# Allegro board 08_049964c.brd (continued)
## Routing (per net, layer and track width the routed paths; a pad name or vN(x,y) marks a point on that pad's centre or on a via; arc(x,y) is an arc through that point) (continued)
VIN: length 4
  TOP w0.508: 55.5,64.9 55.41,64.98 R13.1
  vias: v1(10.41,40.64) v1(10.41,39.75) v1(10.41,38.86) v1(10.41,37.97) v1(10.41,37.08) v1(11.43,40.64) v1(11.43,39.75) v1(11.43,38.86) v1(11.43,37.97) v1(11.43,37.08) v1(12.57,40.64) v1(12.57,39.75) v1(12.57,38.86) v1(13.72,40.64) v1(13.72,39.75) v1(13.72,38.86) v1(49.4,63.37) v1(49.4,62.48) v1(49.4,61.34) v1(49.4,60.45) v1(50.42,63.37) v1(50.42,62.48) v1(50.42,61.34) v1(50.42,60.45) v1(51.56,63.37) v1(51.56,62.48) v1(51.56,61.34) v1(51.56,60.45) v1(52.7,63.37) v1(52.7,62.48) v1(52.7,61.34) v1(52.7,60.45)
VIN1: length 2.5
  TOP w0.305: U1.1 51.18,83.55 51.18,83.57
  vias: v1(32,73.28) v1(32,72.14) v1(32,70.99) v1(32,70.1) v1(33.02,73.28) v1(33.02,72.14) v1(33.02,70.99) v1(33.02,70.1) v1(34.29,73.28) v1(34.29,72.14) v1(34.29,70.99) v1(34.29,70.1) v1(35.43,73.28) v1(35.43,72.14) v1(35.43,70.99) v1(35.43,70.1) v1(47.24,88.9) v1(47.24,88.01) v1(47.24,84.96) v1(47.24,84.07) v1(48.13,88.9) v1(48.13,88.01) v1(48.13,84.96) v1(48.13,84.07) v1(48.95,88.9) v1(48.95,88.01) v1(48.95,84.96) v1(48.95,84.07) v1(49.78,84.96) v1(49.78,84.07)
VIN2: length 12.9
  TOP w0.203: v2(54.41,33.02) 56.32,33.02 56.67,32.67 U3.19
  L3_PWR w0.305: v1(51.82,40.64) 51.56,40.39 51.56,35.04 52.39,34.21 54.1,34.21 54.41,33.91 v2(54.41,33.02)
  vias: v1(22.99,38.35) v1(22.99,37.46) v1(22.99,36.58) v1(22.99,35.69) v1(23.88,38.35) v1(23.88,37.46) v1(23.88,36.58) v1(23.88,35.69) v1(26.8,38.35) v1(26.8,37.46) v1(26.8,36.58) v1(26.8,35.69) v1(27.69,38.35) v1(27.69,37.46) v1(27.69,36.58) v1(27.69,35.69) v1(43.56,40.51) v1(43.56,39.66) v1(44.4,40.52) v1(44.45,39.75) v1(45.29,40.52) v1(45.34,39.75) v1(46.23,40.51) v1(46.23,39.75) v1(46.99,39.5) v1(47.88,39.5)
EN/UVLO: length 44.4
  TOP w0.203: R22.1 v1(33.36,7.53)
  TOP w0.254: v2(52.67,32.06) 52.94,31.8 53.47,31.8 53.78,31.5 54.61,31.5 55.15,30.96 U3.22
  L3_PWR w0.203: v2(52.67,32.06) 52.6,32.13 52.6,32.25 52.14,32.72 49.89,32.72 48.98,31.8 41.87,31.8 38.35,28.28 38.35,18.54 32.68,12.86 32.68,8.22 v1(33.36,7.53)
FAULT: length 81.2
  TOP w0.305: DS3.C v1(2.54,85.85) ; U4.6 25.48,63.89 25.78,63.58 v1(25.78,63.12)
  BOTTOM w0.305: 11.3,85.85 11.3,74.04 21.51,63.83 25.07,63.83 v1(25.78,63.12) ; 11.3,85.85 v1(2.54,85.85) ; 11.3,85.85 38.35,85.85 FAULT.1 44.51,92.01 EN.1
FSEL4A: length 35.7
  TOP w0.203: v2(61.54,33.25) 61.54,33.19 61.15,32.79 60.48,32.79 60.17,32.48 U3.12
  L3_PWR w0.254: v1(56.52,54.36) 56.52,54.1 57.4,53.21 61.09,53.21 61.54,52.76 v2(61.54,33.25)
  BOTTOM w0.305: v1(56.52,54.36) 56.52,54.15 56.21,53.85 51.82,53.85 51.44,54.23 R23.2 R24.2
FSEL4B: length 29.9
  TOP w0.203: v2(52.96,34.92) 53.85,34.04 56.77,34.04 57.67,33.13 U3.17
  L3_PWR w0.254: v1(49.66,53.85) 49.66,52.32 53.06,48.92 53.06,35.03 v2(52.96,34.92)
  BOTTOM w0.305: v1(49.66,53.85) 49.91,54.1 R27.1 R28.1
INTVCC: length 155.5
  TOP w0.203: R17.1 v1(41.36,5.42) ; 54.6,27.88 54.68,27.96
  TOP w0.254: 54.68,27.96 U3.28
  TOP w0.305: v1(54.72,19.93) 54.72,19.96 R29.1
  TOP w0.457: v1(53.52,27.38) 54.02,27.88 54.6,27.88
  TOP w0.508: C19.2 52.86,27.09 53.15,27.38 v1(53.52,27.38)
  L3_PWR w0.203: v1(41.36,5.42) 41.66,5.71 41.66,8.38 40.51,9.52 40.51,26.42 42.93,28.83 v1(43.69,28.83)
  L3_PWR w0.254: v1(53.52,27.38) 53.47,27.38 53.32,27.23 53.18,27.23 53.17,27.21 53.16,27.21 50.8,24.85 50.8,24.13 49.02,22.35 46.99,22.35 ; 46.99,22.35 46.99,27.86 45.42,29.43 44.28,29.43 v1(43.69,28.83) ; 46.99,22.35 46.99,18.16 48.01,17.14 51.9,17.14 54.69,19.93 v1(54.72,19.93)
  L3_PWR w0.305: v1(94.23,57.66) 93.98,57.66 93.6,57.28 87.63,57.28 84.1,53.75 57.63,53.75 57.23,54.15 57.23,54.79 53.98,58.04 v1(49.91,58.04)
  BOTTOM w0.203: v1(94.23,57.66) 94.19,57.62 R19.2
  BOTTOM w0.305: v1(43.69,28.83) 42.67,29.84 42.67,35.43 40.01,38.1 40.01,56.26 42.29,58.55 49.4,58.55 v1(49.91,58.04) R27.2 R23.1
PG1: length 49.5
  TOP w0.203: v2(62.36,25.77) 62.36,25.78 61.93,26.21 61.93,26.59 61.56,26.96 U3.1
  L3_PWR w0.203: v1(93.22,30.23) 92.47,30.23 89.6,27.36 76.26,27.36 74.42,29.2 74.42,32.25 72.76,33.91 70.1,33.91 66.85,30.66 64.06,30.66 63.3,29.9 63.3,26.81 62.36,25.87 v2(62.36,25.77)
  BOTTOM w0.508: PG1.1 92.84,28.45 93.22,28.83 v1(93.22,30.23) R14.1
PG2: length 42.7
  TOP w0.203: v2(62.28,32.53) 62.09,32.53 61.31,31.74 U3.10
  L3_PWR w0.203: v1(94.23,42.25) 94.15,42.16 76.83,42.16 66.29,31.62 63.68,31.62 62.77,32.53 v2(62.28,32.53)
  BOTTOM w0.508: PG2.1 92.75,41.78 R15.1 v1(94.23,42.25)
PG3: length 62.7
  TOP w0.203: v2(62,25.22) 62,25.25 61.88,25.37 61.88,25.53 61.09,26.32 U3.40
  L3_PWR w0.203: v1(94.22,21.88) 94.22,30.87 93.98,31.12 92.71,31.12 89.41,27.81 76.45,27.81 74.88,29.39 74.88,32.44 72.95,34.37 69.91,34.37 66.66,31.12 63.63,31.12 62.74,30.23 62.74,26.97 61.78,26.01 61.78,25.47 62,25.25 v2(62,25.22)
  BOTTOM w0.254: R25.2 61.72,24.87 61.84,24.98 61.84,25.05 v2(62,25.22)
  BOTTOM w0.508: v1(94.22,21.88) R18.1 92.8,21.46 PG3.1
PG4: length 59.8
  TOP w0.203: v2(62.2,33.18) 61.11,32.1 U3.11
  L3_PWR w0.254: v1(94.36,56.01) 93.7,56.67 87.78,56.67 84.33,53.21 62.99,53.21 62.2,52.42 v2(62.2,33.18)
  BOTTOM w0.203: PG4.1 93.18,55.88 R19.1 93.31,56.01 v1(94.36,56.01)
POREN: length 17.2
  TOP w0.203: U3.39 60.17,25.94 60.73,25.37 61.09,25.37 v2(61.23,25.23)
  BOTTOM w0.254: POREN.1 67.82,14.01 61.95,19.88 61.95,20.64 R25.1 60.88,21.71 60.88,22 60.85,22.04 60.85,23.12 61.11,23.39 61.11,25.12 v2(61.23,25.23)
SYNC: length 26.7
  TOP w0.203: U3.33 57.17,25.67 56.77,25.27 54.91,25.27 53.82,24.19 v2(53.82,23.95)
  TOP w0.305: v1(53.59,19.94) 53.94,20.28 R26.1 55.42,22.44 R29.2
  L3_PWR w0.203: v1(53.59,19.94) 53.59,23.72 v2(53.82,23.95)
  BOTTOM w0.203: SYNC.1 50.93,7.75 50.93,15.49 53.59,18.16 v1(53.59,19.94)
UNNAMED_10_CAP_I43_N1: length 24.4
  TOP w0.508: Q2.3 v1(23.37,65.91) ; Q2.1 v1(20.83,66.04)
  BOTTOM w0.254: v1(24.13,74.42) 24.13,73.28 ; 16.76,73.38 v1(16.76,74.42)
  BOTTOM w0.762: Q5.3 24.13,73.28 23.5,73.91 17.3,73.91 16.76,73.38 Q4.3
  BOTTOM w1.016: Q4.3 18.82,71.61 19.43,70.99 19.43,67.44 v1(20.83,66.04)
  vias: v1(17.78,74.42) v1(23.24,74.42)
UNNAMED_10_CAP_I43_N2: length 4
  TOP w0.508: Q2.4 v1(24.64,66.29) ; Q2.2 v1(22.1,66.29)
  BOTTOM w0.762: v1(22.1,66.29) 22.1,67.31 ; v1(24.64,66.29) 24.64,67.44
UNNAMED_10_CAP_I46_N2: length 0.9
  BOTTOM w0.203: v1(15.59,78.36) v1(15.59,79.25)
  vias: v1(13.81,79.25) v1(13.84,78.36) v1(13.81,77.47) v1(13.84,76.58) v1(14.7,79.25) v1(14.7,78.36) v1(14.7,77.47) v1(14.7,76.58) v1(15.59,77.47) v1(15.59,76.58)
UNNAMED_10_CN3P_I18_N1: length 2.3
  TOP w0.508: LED_DRIVE.1 7.87,82.61 D6.C
UNNAMED_10_CN3P_I18_N2: length 10.8
  TOP w0.508: 3.94,82.68 LED_DRIVE.2 5.94,83.79 7.24,85.09 7.24,85.86 ; 7.24,85.86 D8.A ; 7.24,85.86 D7.A
UNNAMED_10_DIO_I19_P: length 3.4
  TOP w0.508: R41.1 7.83,78.34 D6.A
UNNAMED_10_DIO_I22_N: length 2.8
  TOP w0.508: DS3.A 3.67,88.56 4.25,89.14 D8.C
UNNAMED_10_DIO_I50_N: length 2.6
  TOP w0.508: DS2.A 7.78,89.14 D7.C
UNNAMED_10_DIOZNR_I13_P: length 32.1
  TOP w0.305: U4.1 20.46,64.89 v1(19.78,64.21)
  TOP w0.508: R42.1 v1(25.15,60.49) ; R41.2 v1(4.44,74.04)
  BOTTOM w0.508: v1(25.15,60.49) 25.15,62.23 24.21,63.17 21.24,63.17 20.2,64.21 v1(19.78,64.21) 16.81,67.18 16.81,67.52 10.29,74.04 v1(4.44,74.04)
UNNAMED_10_LINLTC4367_I17_OV: length 12.3
  TOP w0.203: v1(16,67.18) 16.26,67.18 16.64,67.56 R44.2
  TOP w0.254: U4.3 21.41,63.89
  TOP w0.305: R45.1 20.95,61.68 20.95,62.23 v1(21.08,62.36) 20.95,62.48 20.95,63.43 21.41,63.89
  BOTTOM w0.203: v1(16,67.18) 16,66.67 19.66,63.02 20.42,63.02 v1(21.08,62.36)
UNNAMED_10_LINLTC4367_I17_SHDNN: length 2
  TOP w0.203: R42.2 25.31,62.19 24.76,62.74 U4.5
UNNAMED_10_LINLTC4367_I17_UV: length 13.8
  TOP w0.203: R44.1 16.38,69.56 16.38,69.25 15.25,68.11 R43.2 v1(15.11,67.21)
  TOP w0.254: U4.2 21.23,64.38 21.1,64.26
  TOP w0.305: v1(20.07,62.36) 20.19,62.48 20.19,63.35 21.1,64.26
  BOTTOM w0.203: v1(15.11,67.21) 15.11,66.8 19.56,62.36 v1(20.07,62.36)
UNNAMED_11_CAP_I15_N2: length 2.4
  TOP w0.508: C4.2 TIMER.3
UNNAMED_11_CAP_I88_N2: length 21.5
  TOP w0.305: R9.2 62.8,82.1 64.64,80.26 R49.2 65.91,80.32 65.91,81.79 66.29,82.17 80.09,82.17 80.39,82.47 80.39,83.06
  vias: v1(62.87,62.99) v1(62.87,62.1) v1(62.87,60.96) v1(62.87,60.07) v1(63.88,62.99) v1(63.88,62.1) v1(63.88,60.96) v1(63.88,60.07) v1(65.02,62.99) v1(65.02,62.1) v1(65.02,60.96) v1(65.02,60.07) v1(66.17,62.99) v1(66.17,62.1) v1(66.17,60.96) v1(66.17,60.07) v1(80.39,88.14) v1(80.39,86.87) v1(80.39,85.6) v1(80.39,84.33) v1(81.66,88.14) v1(81.66,86.87) v1(81.66,85.6) v1(81.66,84.33) v1(82.93,88.14) v1(82.93,86.87) v1(82.93,85.6) v1(82.93,84.33) v1(84.33,88.14) v1(84.33,86.87) v1(84.33,85.6) v1(84.33,84.33) v1(87.5,67.95) v1(87.5,66.67) v1(87.5,65.41) v1(87.5,64.14) v1(87.5,62.86) v1(88.77,65.41) v1(88.77,64.14) v1(88.77,62.86) v1(90.04,65.41) v1(90.04,64.14) v1(90.04,62.86) v1(91.31,66.67) v1(91.44,65.41) v1(91.44,64.14) v1(91.44,62.86) v1(91.95,67.82)
UNNAMED_11_CN3P_I14_N1: length 3.8
  TOP w0.508: CHRG_LED.1 53.07,90.47 DS1.C
UNNAMED_11_CN3P_I14_N2: length 14.8
  TOP w0.254: U1.7 57.52,82.05 v1(57.85,81.72)
  L3_PWR w0.305: CHRG_LED.2 57.85,90.77 v1(57.85,81.72)
UNNAMED_11_CN3P_I18_N2: length 62.4
  TOP w0.254: U1.6 57.13,81.55 v1(57.79,80.9)
  L3_PWR w0.305: TIMER.2 18.7,94.01 19.3,94.61 19.3,96.77 20.17,97.64 58.19,97.64 58.93,96.9 58.93,81.28 58.56,80.92 57.8,80.92 v1(57.79,80.9)
UNNAMED_11_CN3P_I31_N1: length 2.3
  TOP w0.254: R4.2 ICHARGE.1
UNNAMED_11_CN3P_I31_N2: length 32.8
  TOP w0.254: ICHARGE.2 34.38,93.22 R2.2 33.11,87.8 41.02,79.88 49.99,79.88 52.65,82.54 52.91,82.54 52.91,82.55 U1.3
UNNAMED_11_CN3P_I31_N3: length 2.3
  TOP w0.508: ICHARGE.3 R7.2
UNNAMED_11_CN3P_I34_N1: length 6.8
  TOP w0.305: NTC.1 21.34,96.01 P2.1
UNNAMED_11_CN3P_I34_N2: length 37
  TOP w0.254: P2.2 30.61,91.35 30.61,89.03 41.02,78.61 53.98,78.61 54.19,78.83 R5.1
  TOP w0.305: R5.1 54.19,80.56 53.69,81.06 U1.5
UNNAMED_11_CN3P_I34_N3: length 2.3
  TOP w0.508: R6.2 P2.3
UNNAMED_11_CN3P_I68_N2: length 24.3
  TOP w0.203: CHARGER_EN.1 41.56,94.01 EN.2
  TOP w0.254: v1(51.94,82.8) 52.19,83.05 U1.2
  L3_PWR w0.305: EN.2 48.35,94.01 51.94,90.42 v1(51.94,82.8)
UNNAMED_11_CN3P_I82_N1: length 3.2
  TOP w0.305: R9.1 61.98,78.11 P13.1
UNNAMED_11_CN3P_I82_N3: length 3.3
  TOP w0.305: R49.1 67.75,78.36 P13.3
UNNAMED_11_CNTP1P_I56_N1: length 2.6
  TOP w0.254: PROG.1 31.41,95.54 R2.1
UNNAMED_11_DIOLED_I76_P: length 2.3
  TOP w0.508: R11.1 51.58,86.67 DS1.A
UNNAMED_11_LINLTC4079_I19_FB: length 14.8
  TOP w0.254: U1.9 58.74,83.05 R8.2 60.63,82.1 60.83,81.9 60.83,76.58 61.34,76.07 64.01,76.07 64.74,76.8 P13.2
UNNAMED_11_LINLTC4079_I19_FBG: length 4.8
  TOP w0.254: U1.8 58.17,82.55 58.55,82.17 58.55,80.52 58.86,80.2 R8.1
UNNAMED_11_LINLTC4079_I19_NTCBI: length 3.1
  TOP w0.254: R5.2 52.49,81.63 52.91,82.05 U1.4
UNNAMED_11_LINLTC4412_I41_GATE: length 10
  TOP w0.305: U2.5 v1(57.79,65.91)
  TOP w0.508: Q3.4 v1(57.02,59.18)
  L3_PWR w0.305: v1(57.02,59.18) 57.05,59.21 57.05,65.18 v1(57.79,65.91)
UNNAMED_11_LINLTC4412_I41_STAT: length 2.2
  TOP w0.508: U2.4 56.6,67.52 57.11,68.03 R13.2
UNNAMED_12_CAP_I13_N1: length 11.9
  TOP w0.203: v2(54.36,30.1) 54.49,29.96 U3.24
  TOP w0.305: C30.1 48.73,29.51 R35.1 R37.2 49.39,27.23 49.39,27.19 49.53,27.05 v1(49.53,26.92)
  L3_PWR w0.305: v2(54.36,30.1) 54.36,29.98 53.58,29.21 52.33,29.21 50.05,26.92 v1(49.53,26.92)
UNNAMED_12_CAP_I27_N1: length 12.6
  TOP w0.203: U3.26 53.57,28.96 53.48,29.04 53,29.04 52.58,28.63 v2(52.58,28.45)
  TOP w0.305: C29.1 45.77,23.92 R33.1 48.47,23.92 R38.1 v1(48.68,25.02)
  L3_PWR w0.305: v1(48.68,25.02) 49.15,25.02 v2(52.58,28.45)
UNNAMED_12_CAP_I38_N1: length 12.5
  TOP w0.203: v2(53.47,30.1) 54.11,29.46 U3.25
  TOP w0.305: R39.1 v1(48.68,26.92) 47.41,26.92 R34.1 47.19,27.14 C28.1
  L3_PWR w0.305: v1(48.68,26.92) 48.82,27.06 48.82,27.22 49.24,27.64 49.97,27.64 52.18,29.84 53.21,29.84 v2(53.47,30.1)
UNNAMED_12_CAP_I47_N2: length 32.4
  TOP w0.254: 57.02,24.75 57.31,24.75 57.67,25.11 U3.34
  TOP w0.305: 55.63,24.38 55.63,24.5 55.88,24.75 57.02,24.75
  L3_PWR w1.016: 68.83,27.3 68.83,27.18 68.81,27.15 68.81,22.98 65.07,19.25 57.33,19.25 54.86,21.72 v1(54.86,23.58) v1(54.86,24.26) ; 68.83,27.3 68.83,28.19 v1(68.96,28.32) v1(69.85,28.32) 68.83,27.3
  BOTTOM w0.762: 69.6,27.81 69.09,28.32 v1(68.96,28.32) ; 69.6,27.81 69.85,28.07 v1(69.85,28.32) ; 69.6,27.81 R54.1
UNNAMED_12_CAP_I51_N1: length 13.4
  TOP w0.203: v2(53.24,28.46) 53.24,28.46 U3.27
  TOP w0.305: C27.1 45.77,22.44 R32.1 48.59,22.44 R36.1 v1(48.68,23.11)
  L3_PWR w0.305: v1(48.68,23.11) 49.76,24.19 49.76,24.73 52.77,27.74 52.87,27.74 53.21,28.08 53.21,28.44 v2(53.24,28.46)
UNNAMED_12_CAP_I102_N1: length 51.3
  TOP w0.203: U3.21 55.25,31.46 54.73,31.98 53.98,31.98 53.67,32.28 53.44,32.28 v2(52.88,32.84)
  TOP w0.254: P5.2 P5.1 25.18,8.09 C10.1 30.57,8.09 TRKSS1.1
  L3_PWR w0.203: TRKSS1.1 30.86,8.38 30.86,16.13 37.9,23.16 37.9,28.47 41.68,32.26 48.79,32.26 49.7,33.17 52.55,33.17 v2(52.88,32.84)
UNNAMED_12_CAP_I105_N1: length 58.8
  TOP w0.203: v2(53.57,32.92) 53.68,32.92 54.16,32.44 54.81,32.44 55.15,32.1 U3.20
  TOP w0.254: TRKSS2.1 16.93,8.25 C11.1 13.75,8.09 P6.1 P6.2
  L3_PWR w0.203: v2(53.57,32.92) 53.57,33.07 53.01,33.63 49.51,33.63 48.6,32.72 41.49,32.72 37.44,28.66 37.44,23.72 28.45,14.73 27.16,14.73 21.07,8.64 19.69,8.64 TRKSS2.1
UNNAMED_12_CAP_I135_N1: length 0.9
  TOP w0.203: C25.1 65.12,29.16 R21.2
UNNAMED_12_CAP_I136_N1: length 0.9
  TOP w0.203: C24.1 65.12,28.24 R20.2
UNNAMED_12_CAP_I137_N1: length 6.5
  TOP w0.203: C22.1 53.89,23.17 53.26,23.79 53.26,25.6 53.54,25.88 54.42,25.88 54.43,25.89 54.45,25.89 54.88,26.32 U3.31
UNNAMED_12_CAP_I161_N1: length 54.2
  TOP w0.203: R22.2 v1(33.36,9.23)
  TOP w0.254: 54.97,30.5 55.01,30.46 U3.23
  TOP w0.305: 54.1,30.86 54.6,30.86 54.96,30.5 54.97,30.5
  TOP w0.508: 54.1,30.86 53.51,30.86 53.22,31.15 C17.1 v1(51.94,31.98)
  L3_PWR w0.203: v1(51.94,31.98) 51.2,31.98 50.57,31.34 42.06,31.34 38.81,28.09 38.81,16.59 33.36,11.14 v1(33.36,9.23)
  BOTTOM w0.508: v1(51.94,31.98) 51.4,31.44 51.39,31.44 51.14,31.19 49.96,31.19 49.48,31.67 49.48,32.48 51.51,34.51 51.51,35.86 51.12,36.26 D9.C
  BOTTOM w0.635: D9.C 51.14,36.63 R3.2 D3.C
UNNAMED_12_CAP_I223_N2: length 3.6
  TOP w0.305: C21.2 57.4,34.58 57.4,34.16 58.17,33.4 U3.16
UNNAMED_12_CN3P_I211_N1: length 3.2
  TOP w0.203: P14.1 38.39,8.25 R55.1
UNNAMED_12_CN3P_I211_N2: length 32
  TOP w0.203: v1(47.75,19.56) 47.75,19.43 45.59,17.27 45.59,11.05 41.53,6.98 RUN3.1 39.4,6.26 P14.2 ; U3.30 54.98,26.96 54.29,26.28 53.74,26.28 v2(53.47,26.55)
  L3_PWR w0.203: v1(47.75,19.56) 47.75,20.19 51.69,24.13 51.69,24.77 v2(53.47,26.55)
UNNAMED_12_CN3P_I211_N3: length 2.9
  TOP w0.203: P14.3 39.47,4.26 R17.2
UNNAMED_12_CNTP1P_I217_N1: length 27.5
  TOP w0.203: v2(53.92,25.27) 54.37,25.27 54.75,25.65 56.42,25.65 56.67,25.91 U3.32
  L3_PWR w0.203: v1(48.51,17.83) 49.28,18.59 49.28,20.19 52.83,23.75 52.83,24.18 v2(53.92,25.27)
  BOTTOM w0.203: RST_N.1 45.85,10.41 46.99,11.56 48.97,11.56 50.04,12.63 50.04,16.31 v1(48.51,17.83)
UNNAMED_12_ICLT8603_I134_BST1: length 2.1
  TOP w0.203: R20.1 63.11,28.46 U3.4
UNNAMED_12_ICLT8603_I134_BST2: length 2.1
  TOP w0.203: R21.1 63.13,28.96 U3.5
UNNAMED_12_ICLT8603_I134_GATE4: length 14.9
  TOP w0.203: v2(58.09,34.54) 58.09,34.5 58.17,34.42 58.17,34.04 58.67,33.53 U3.15
  TOP w0.61: Q1.4 v1(59.31,45.08)
  L3_PWR w0.508: v2(58.09,34.54) 58.09,43.86 v1(59.31,45.08)
UNNAMED_12_ICLT8603_I134_ISN4: length 16.1
  TOP w0.203: v2(52.32,35.43) 52.2,35.31 52.2,34.67 53.26,33.6 56.56,33.6 57.17,32.99 U3.18
  L3_PWR w0.305: v2(52.32,35.43) 52.32,40.14 52.53,40.35 52.53,43.13 v1(51.84,43.81)
UNNAMED_12_ICLT8603_I134_RT: length 12.5
  TOP w0.203: v2(54.08,26.78) 54.64,27.34 54.9,27.34 55.02,27.46 U3.29
  TOP w0.254: R31.2 48.68,19.62 v1(48.62,19.56)
  L3_PWR w0.254: v1(48.62,19.56) 48.62,20.29 52.2,23.88 52.2,24.43 53.7,25.94 53.72,25.94 54.07,26.3 54.07,26.78 v2(54.08,26.78)
VOUT1: length 63.4
  TOP w0.305: R33.2 45.77,25.61 C29.2 v1(44.79,25.57)
  L3_PWR w0.305: v1(71.49,23.49) 71.43,23.49 65.71,17.78 58.7,17.78 56.98,16.05 47.42,16.05 45.47,18.01 45.47,24.89 v1(44.79,25.57)
  BOTTOM w0.508: R15.2 R14.2 94.11,33.11 94.61,32.6 94.61,24.09 94.11,23.58 R18.2 90.84,23.58 VOUT1.1
  vias: v1(74.68,23.24) v1(74.68,22.35) v1(75.69,23.24) v1(75.69,22.35) v1(76.71,23.24) v1(76.71,22.35) v1(85.47,25.65) v1(85.47,24.77) v1(85.47,23.75) v1(85.47,22.86) v1(86.61,25.65) v1(86.61,24.77) v1(86.61,23.75) v1(86.61,22.86) v1(87.63,25.65) v1(87.63,24.77) v1(87.63,23.75) v1(87.63,22.86) v1(91.82,25.65) v1(91.82,24.77)
VOUT2: length 59.3
  TOP w0.279: v2(62.37,31.87) 62.31,31.81 62.31,31.32 61.95,30.96 U3.9
  TOP w0.305: R34.2 45.77,28.79 C28.2 v1(44.72,28.74)
  L3_PWR w0.305: v1(71.63,31.75) 71.63,30.82 70.76,29.95 70.76,27.94 70.74,27.92 70.74,27.79 69.72,26.77 69.72,22.61 65.45,18.34 58.34,18.34 56.62,16.61 47.78,16.61 46.23,18.16 46.23,27.3 44.79,28.74 v1(44.72,28.74)
  BOTTOM w0.203: C61.P 75.69,35.05 v1(74.8,34.16)
  BOTTOM w0.305: v1(65.49,32.28) 65.49,32.13 64.06,30.7 C18.2 62.68,30.7 62.37,31.01 v2(62.37,31.87)
  vias: v1(75.82,34.16) v1(75.82,33.35) v1(76.83,34.16) v1(76.83,33.35) v1(85.47,38.23) v1(85.47,37.34) v1(85.47,36.32) v1(85.47,35.43) v1(86.61,38.23) v1(86.61,37.34) v1(86.61,36.32) v1(86.61,35.43) v1(87.63,38.23) v1(87.63,37.34) v1(87.63,36.32) v1(87.63,35.43)
VOUT3: length 24.5
  TOP w0.305: v1(44.7,20.79) C27.2 45.77,20.74 R32.2
  L3_PWR w0.305: v1(62.13,17.02) 59.11,17.02 57.58,15.49 47.12,15.49 44.7,17.91 v1(44.7,20.79)
  vias: v1(62.1,15.11) v1(62.17,14.22) v1(62.18,13.33) v1(62.99,15.11) v1(62.99,14.22) v1(62.99,13.33) v1(63.88,15.11) v1(63.88,14.22) v1(63.88,13.33) v1(85.34,11.94) v1(85.34,11.05) v1(85.34,10.16) v1(86.23,11.94) v1(86.23,11.05) v1(86.23,10.16) v1(87.12,11.94) v1(87.12,11.05) v1(87.12,10.16)
VOUT4: length 17.6
  TOP w0.305: v1(50.29,32) 50.33,31.97 C30.2 50.33,29.51 R35.2
  BOTTOM w0.203: v1(50.29,32) 52.55,34.26 53.57,34.26 55.45,36.14 60.53,36.14 62.36,37.97 62.87,37.97
  vias: v1(65.72,39.24) v1(65.72,38.35) v1(65.73,37.47) v1(66.47,39.24) v1(66.54,38.35) v1(66.55,37.46) v1(67.31,39.24) v1(67.35,38.35) v1(67.36,37.46) v1(73.23,49.94) v1(73.23,49.05) v1(73.23,48.03) v1(73.23,47.02) v1(74.22,49.91) v1(74.22,49.02) v1(74.22,48.01) v1(74.22,46.99) v1(76.89,49.91) v1(76.89,49.02) v1(76.89,48.01) v1(76.89,46.99) v1(77.88,49.94) v1(77.88,49.05) v1(77.88,48.03) v1(77.88,47.02) v1(80.85,49.94) v1(80.85,49.05) v1(80.85,48.03) v1(80.85,47.02) v1(81.84,49.91) v1(81.84,49.02) v1(81.84,48.01) v1(81.84,46.99) v1(84.51,49.91) v1(84.51,49.02) v1(84.51,48.01) v1(84.51,46.99) v1(85.45,49.94) v1(85.45,49.05) v1(85.45,48.03) v1(85.45,47.02) v1(87.63,53.34) v1(88.57,49.78) v1(88.57,48.77) v1(89.59,49.78) v1(89.59,48.77) v1(90.6,49.78) v1(90.6,48.77) v1(91.62,49.78) v1(91.62,48.77)

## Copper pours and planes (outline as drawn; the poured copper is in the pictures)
AGND on TOP: 38.86,97.54 95.12,97.54 95.12,1.65 94.74,1.27 2.03,1.27 1.27,2.03 1.27,34.92 1.27,82.42 1.4,82.55 1.4,97.54 21.59,97.54 21.59,96.65 22.61,95.63 26.8,95.63 26.8,88.65 26.92,88.52 29.46,88.52 30.48,87.5 31.37,87.5 31.37,87.38 38.99,79.76 39.37,79.76 41.15,77.98 51.44,77.98 51.82,78.36 51.82,80.01 40.77,80.01 40.77,80.39 34.54,86.61 34.54,88.52 34.67,88.65 35.94,88.65 36.07,88.77 36.07,94.87 35.94,95 38.86,95 ; 12 cut-outs
AGND on BOTTOM: 95.12,97.66 95.12,1.27 1.27,1.27 1.27,8.89 1.27,97.66 ; 3 cut-outs
AGND on L2_GND: 95.12,97.79 95.12,1.52 94.87,1.27 1.52,1.27 1.27,1.52 1.27,8.89 1.27,8.89 1.27,97.79
AGND on L3_PWR: 95.12,97.54 95.12,2.16 94.49,1.52 2.79,1.52 1.4,2.92 1.4,97.54
PVIN on TOP: 60.83,21.46 60.71,21.34 59.31,21.34 59.18,21.46 59.18,25.27 59.44,25.27 59.74,24.97 59.74,24.08 59.94,23.88 60.83,23.88
PVIN on TOP: 59.31,31.75 59.05,31.75 59.05,32.26 58.93,32.38 58.93,33.78 58.55,34.16 58.55,35.69 58.04,36.2 58.04,38.86 58.17,38.99 60.45,38.99 60.58,38.86 60.58,35.81 60.1,35.33 60.1,33.55 59.44,32.89 59.44,31.88
PVIN on BOTTOM: 60.45,36.96 62.1,38.61 62.1,44.2 61.98,44.32 58.17,44.32 58.04,44.2 58.04,37.08 58.17,36.96
VIN on TOP: 56.26,60.2 54.23,60.2 52.32,58.29 43.82,58.29 40.89,61.21 40.89,66.29 41.27,66.67 45.21,66.67 46.74,65.15 57.15,65.15 57.66,64.64 57.66,64.14 56.26,62.74
VIN on TOP: 13.84,41.02 5.21,41.02 4.95,40.77 4.95,33.27 5.46,32.77 13.34,32.77 13.59,33.02 13.59,38.23 14.1,38.73 14.1,40.77
VIN on BOTTOM: 6.48,34.29 6.48,40.51 6.98,41.02 14.1,41.02 14.22,40.89 14.22,36.96 13.97,36.7 10.79,36.7 10.41,36.32 10.41,34.29
VIN on BOTTOM: 57.66,63.37 57.66,60.07 56.64,60.07 55.88,59.31 48.9,59.31 48.64,59.56 48.64,64.39 48.9,64.64 55.5,64.64 56.77,63.37
VIN on L3_PWR: 12.95,33.66 6.73,33.66 4.83,35.56 4.83,39.75 11.18,46.1 11.18,52.96 14.73,56.52 34.8,56.52 42.93,64.64 52.83,64.64 53.09,64.39 53.09,59.94 52.83,59.69 45.85,59.69 36.58,50.42 18.92,50.42 17.02,48.51 17.02,37.72
VIN1 on TOP: 22.99,73.69 22.99,68.45 24.89,68.45 25.02,68.33 25.65,68.33 25.91,68.07 25.91,64.9 25.53,64.52 24.51,64.52 24.51,64.26 25.91,64.26 26.29,63.88 34.8,63.88 36.45,62.23 39.88,62.23 40.26,62.61 40.26,69.28 34.48,75.06 25.65,75.06 24.33,73.74 23.04,73.74
VIN1 on TOP: 49.78,88.77 49.78,85.47 50.67,84.58 53.59,84.58 53.85,84.33 53.85,83.44 45.59,83.44 45.21,83.82 45.21,88.9 45.47,89.15 49.4,89.15
VIN1 on BOTTOM: 36.2,75.56 36.2,69.47 35.56,68.83 31.88,68.83 31.24,69.47 31.24,73.79 29.46,75.56 23.49,75.56 23.49,81.86 23.55,81.91 29.84,81.91
VIN1 on BOTTOM: 50.67,83.19 50.55,83.06 46.99,83.06 46.61,83.44 46.61,89.28 46.99,89.66 50.42,89.66 50.67,89.41
VIN1 on L3_PWR: 35.94,77.34 41.66,83.06 50.29,83.06 50.67,83.44 50.67,89.28 50.42,89.53 38.48,89.53 29.46,80.52 29.46,69.72 29.84,69.34 35.31,69.34 35.94,69.98
VIN2 on TOP: 52.2,40 52.2,41.27 51.82,41.66 43.43,41.66 43.18,41.4 43.18,37.59 43.31,37.46 48.26,37.46 48.39,37.34 50.93,37.34 51.05,37.46 51.05,38.86
VIN2 on TOP: 28.32,35.05 28.32,40.64 27.94,41.02 20.07,41.02 19.81,40.77 19.81,34.54 20.07,34.29 27.56,34.29
VIN2 on BOTTOM: 43.31,38.99 43.31,40.64 43.69,41.02 48.13,41.02 48.64,40.51 48.64,39.5 48.01,38.86 48.01,37.97 47.12,37.97 47.12,38.61 46.99,38.73 43.56,38.73
VIN2 on L3_PWR: 46.99,38.1 40.01,38.1 36.32,34.42 23.11,34.42 22.35,35.18 22.35,38.99 22.73,39.37 35.69,39.37 38.16,41.85 47.43,41.85 48.26,41.02 48.26,39.37
UNNAMED_5_CAP_I17_N2 on BOTTOM: 62.23,45.47 61.98,45.21 57.4,45.21 57.28,45.34 57.28,49.66 57.4,49.78 61.98,49.78 62.23,49.53
UNNAMED_10_CAP_I43_N1 on BOTTOM: 28.96,66.42 28.96,64.14 28.58,63.75 20.7,63.75 20.45,64.01 20.45,66.67 20.7,66.93 21.08,66.93 21.46,66.55 21.46,66.04 21.84,65.66 22.35,65.66 22.67,65.98 22.67,66.61 22.73,66.67 24,66.67 24,65.91 24.26,65.66 25.02,65.66 25.27,65.91 25.27,66.67 28.7,66.67
UNNAMED_10_CAP_I43_N1 on BOTTOM: 16,70.23 16,74.3 16.76,75.06 23.88,75.06 24.89,74.04 24.89,70.1 23.37,70.1 23.37,73.15 23.11,73.41 17.78,73.41 17.53,73.15 17.53,70.1 16.13,70.1
UNNAMED_10_CAP_I43_N1 on L3_PWR: 16,74.8 16,70.1 16.38,69.72 26.67,69.72 27.05,70.1 27.05,74.8 26.67,75.18 16.38,75.18
UNNAMED_10_CAP_I43_N2 on TOP: 24.38,64.9 24.38,65.91 24.26,66.04 24.26,67.82 25.4,67.82 25.53,67.69 25.53,65.15 25.15,64.77 24.51,64.77
UNNAMED_10_CAP_I43_N2 on BOTTOM: 25.78,70.61 27.56,70.61 27.94,70.99 27.94,73.02 28.07,73.15 29.34,73.15 29.46,73.02 29.46,69.98 28.96,69.47 28.96,67.56 28.83,67.44 25.15,67.44 24.89,67.18 21.59,67.18 20.57,68.2 20.57,73.02 21.97,73.02 22.1,72.9 22.1,70.1 22.61,69.6 25.4,69.6 25.65,69.85 25.65,70.48
UNNAMED_10_CAP_I46_N1 on BOTTOM: 5.59,61.47 5.59,58.42 5.21,58.04 2.54,58.04 2.29,58.29 2.29,61.47 2.41,61.59 5.46,61.59
UNNAMED_10_CAP_I46_N2 on TOP: 5.84,68.2 5.84,74.42 11.18,79.76 21.21,79.76 22.48,78.49 22.48,68.45 22.35,68.33 20.45,68.33 20.45,70.87 16.13,70.87 15.88,70.61 15.88,69.72 15.62,69.47 14.48,69.47 12.32,67.31 6.73,67.31
UNNAMED_10_CAP_I46_N2 on BOTTOM: 3.05,71.12 3.43,71.5 9.52,71.5 9.91,71.12 9.91,64.52 9.27,63.88 3.17,63.88 3.05,64.01
UNNAMED_10_CAP_I46_N2 on BOTTOM: 13.59,76.2 14.22,75.56 21.84,75.56 21.97,75.69 21.97,81.86 21.92,81.91 13.84,81.91 13.59,81.66
UNNAMED_10_DIOZNR_I12_N on TOP: 15.75,66.55 15.75,61.34 15.49,61.09 13.46,61.09 13.34,61.21 13.34,66.42 13.46,66.55
UNNAMED_10_DIOZNR_I13_P on TOP: 22.35,65.53 22.35,64.9 22.23,64.77 20.83,64.77 19.94,63.88 18.03,63.88 17.4,64.52 17.4,67.18 17.65,67.44 17.65,68.83 17.78,68.96 19.56,68.96 19.69,68.83 19.69,67.18 21.21,65.66 22.23,65.66
UNNAMED_11_CAP_I88_N2 on TOP: 56.52,83.44 58.29,83.44 58.67,83.06 84.84,83.06 85.22,83.44 85.22,90.04 84.45,90.8 62.04,90.8 59.75,88.52 59.75,87.19 56.52,83.95
UNNAMED_11_CAP_I88_N2 on TOP: 68.33,58.29 72.26,62.23 92.2,62.23 92.58,62.61 92.58,69.09 91.19,70.48 68.45,70.48 66.29,68.33 66.29,65.79 65.79,65.28 58.67,65.28 58.42,65.02 58.42,64.01 59.18,63.25 59.18,58.42 59.31,58.29
UNNAMED_11_CAP_I88_N2 on BOTTOM: 58.42,63.25 59.31,63.25 60.83,64.77 66.29,64.77 66.55,64.52 66.55,59.94 65.79,59.18 60.33,59.18 59.44,60.07 58.42,60.07
UNNAMED_11_CAP_I88_N2 on L3_PWR: 84.96,62.61 92.46,62.61 93.09,63.25 93.09,70.99 92.46,71.63 87.76,71.63 86.36,73.02 86.36,88.27 85.47,89.15 79.25,89.15 78.49,88.39 78.49,69.09
UNNAMED_12_CAP_I47_N2 on TOP: 55.37,23.37 55.12,23.11 54.74,23.11 54.51,23.34 54.51,24.66 54.86,25.02 56.01,25.02 56.18,24.84 56.18,23.39 56.16,23.37
UNNAMED_12_CAP_I47_N2 on BOTTOM: 69.22,29.72 69.98,29.72 69.98,29.21 70.23,28.96 70.23,27.69 69.98,27.43 69.22,27.43 68.58,28.07 68.58,28.58 69.22,29.21
UNNAMED_12_CAP_I135_N2 on TOP: 60.96,30.1 60.96,29.34 62.74,29.34 62.99,29.59 65.53,29.59 66.29,28.83 70.74,28.83 70.87,28.96 70.87,30.1 70.23,30.73 63.25,30.73 62.61,30.1
UNNAMED_12_CAP_I136_N2 on TOP: 61.85,27.81 61.09,27.81 61.09,28.19 62.64,28.19 63.14,27.69 70.74,27.69 70.99,27.43 70.99,26.29 70.87,26.16 64.13,26.16 63.25,27.05 62.61,27.05
UNNAMED_12_CAP_I178_N1 on TOP: 50.55,52.2 50.55,45.72 50.67,45.59 52.45,45.59 54.48,47.62 60.45,47.62 60.83,48.01 60.83,50.04 60.96,50.16 65.28,50.16 65.53,50.42 65.53,52.96 65.21,53.28 52.64,53.28 51.56,52.2
UNNAMED_12_CAP_I178_N2 on TOP: 61.98,49.28 61.98,45.21 61.21,44.45 58.42,44.45 58.42,39.62 60.2,39.62 60.83,40.26 60.83,41.4 61.09,41.66 65.66,41.66 65.94,41.94 65.94,48.87 65.53,49.28
UNNAMED_12_CAP_I197_N2 on TOP: 14.86,40.64 14.86,33.78 15.11,33.53 18.8,33.53 18.92,33.66 18.92,40.64 18.54,41.02 15.24,41.02
UNNAMED_12_ICLT8603_I134_ISN4 on TOP: 49.28,44.96 48.77,45.47 48.77,52.7 48.51,52.96 42.67,52.96 42.16,52.45 42.16,43.94 43.43,42.67 52.07,42.67 52.2,42.8 52.2,44.7 51.94,44.96
UNNAMED_12_ICLT8603_I134_SW3 on TOP: 58.8,26.54 58.8,25.91 58.93,25.78 58.93,21.21 59.44,20.7 59.44,16.76 59.31,16.64 58.04,16.64 57.91,16.76 57.91,22.86 58.17,23.11 58.17,24.64 58.04,24.77 58.42,25.15 58.42,25.78 58.55,25.91 58.55,26.54
VOUT1 on TOP: 91.82,27.43 92.33,26.92 92.33,22.73 91.82,22.23 84.45,22.23 84.07,22.61 84.07,27.05 84.45,27.43
VOUT1 on TOP: 71.25,24.13 71.75,24.64 76.58,24.64 77.09,24.13 77.09,21.46 76.71,21.08 70.23,21.08 68.58,22.73 65.91,22.73 65.86,22.78 65.86,24.05 65.94,24.13
VOUT1 on BOTTOM: 69.09,25.91 71.12,25.91 73.53,23.49 81.41,23.49 82.55,22.35 82.55,19.05 82.3,18.8 74.29,18.8 74.04,19.05 74.04,20.45 70.48,24 69.47,24 68.96,24.51 68.96,25.78
VOUT1 on L3_PWR: 74.29,24.64 74.29,21.08 74.55,20.83 93.09,20.83 93.47,21.21 93.47,26.92 92.96,27.43 80.01,27.43 77.47,24.89 74.55,24.89
VOUT2 on TOP: 92.07,40.26 92.58,39.75 92.58,35.56 92.07,35.05 84.71,35.05 84.33,35.43 84.33,39.88 84.71,40.26
VOUT2 on TOP: 65.15,33.4 68.45,33.4 70.36,35.31 77.09,35.31 77.22,35.18 77.22,31.75 76.96,31.5 71.63,31.5 71.12,32 65.15,32
VOUT2 on BOTTOM: 74.42,37.72 82.3,37.72 82.55,37.46 82.55,34.29 81.28,33.02 74.17,33.02 71.88,30.73 69.09,30.73 68.96,30.86 68.96,32.13 69.47,32.64 70.48,32.64 74.04,36.2 74.04,37.34
VOUT2 on L3_PWR: 82.42,30.1 86.61,34.29 92.2,34.29 92.71,34.8 92.71,40 92.33,40.39 80.77,40.39 75.56,35.18 75.56,35.15 74.7,35.15 74.4,34.85 74.4,33.78 78.08,30.1
VOUT3 on TOP: 63.12,19.05 64.39,19.05 64.77,18.67 64.77,13.33 64.39,12.95 60.96,12.95 60.71,13.21 60.71,16.64 60.58,16.76 60.58,20.45 61.72,20.45
VOUT3 on TOP: 91.82,14.76 92.32,14.26 92.32,10.05 92.32,9.77 91.95,9.4 84.61,9.4 84.07,9.93 84.07,14.38 84.45,14.76
VOUT3 on L3_PWR: 60.45,15.11 60.45,8 61.72,6.73 91.95,6.73 92.58,7.37 92.58,14.99 92.07,15.49 60.83,15.49
VOUT4 on TOP: 67.69,36.7 67.69,38.86 68.45,39.62 68.45,41.53 66.42,41.53 66.04,41.15 61.59,41.15 61.47,41.02 61.47,36.07 67.06,36.07
VOUT4 on TOP: 84.84,50.48 86.26,51.91 86.26,54.26 86.74,54.74 92.2,54.74 92.58,54.36 92.58,48.13 92.07,47.62 89.28,47.62 85.72,44.07 73.02,44.07 72.52,44.58 72.52,50.1 72.9,50.48
VOUT4 on BOTTOM: 67.69,37.21 67.82,37.34 67.82,39.75 67.44,40.13 65.91,40.13 65.53,40.51 65.53,50.93 62.48,53.98 58.42,53.98 58.42,52.83 58.29,52.7 57.53,52.7 57.4,52.58 57.4,50.55 57.53,50.42 62.23,50.42 62.61,50.04 62.61,37.46 62.87,37.21
VOUT4 on BOTTOM: 51.44,89.66 73.41,89.66 74.55,88.52 74.55,51.18 75.44,50.29 82.04,50.29 82.17,50.16 82.17,46.1 81.85,45.78 69.41,45.78 69.09,46.1 69.09,84.33 68.2,85.22 52.83,85.22 52.45,85.6 51.44,85.6 51.31,85.72 51.31,89.53
VOUT4 on L3_PWR: 64.39,37.59 64.9,37.08 67.69,37.08 68.2,37.59 68.2,40.64 72.07,44.51 85.66,44.51 88.65,47.5 92.33,47.5 92.58,47.75 92.58,53.47 91.95,54.1 88.27,54.1 84.45,50.29 69.09,50.29 64.39,45.59

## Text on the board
Ref Des/Silkscreen Bottom: VIN | AGND | REVERSE PROTECTED | LTC4367 VOUT | UV PROTECTED | OV PROTECTED | LTC4367 BLOCK | GATE ON | EMI FILTER 2 | 0V TO 4.5V | 4.5V TO 36V | 36V TO 100V | -40 TO 0V | VBATT
Ref Des/Silkscreen Top: ON | GND | OFF | LED_DRIVE | TRKSS2 | EMI FILTER 1 | LTC4367 BLOCK | EXT | NTC | INT | TRKSS1 | RUN3 | 100mA | LTC4412 BLOCK | LTC4079 BLOCK | LT8603 BLOCK | FAULT | VIN | 50mA | 4.2V | VBATT | 4.1V | * SEE DEMO MANUAL FOR DETAILS OF | OUTPUT VOLTAGE AND CURRENT RATINGS | cm | 1 | T-BOX POWER SYSTEM | EVALUATION BOARD Z
PAGE_OUTLINE: B | B1 | C | ECR-082786 | ECR-082847 | ECR-084163 | 26OCT18 | 30OCT18 | 29JAN19 | FBALAT | EVAL BOARD Z
XSECTION_CHART: STACKUP TABLE | Unit = Mils | # | 1 | 2 | 3 | 4 | NAME | SILSKCREEN_TOP | SOLDERMASK_TOP | TOP | L2_GND | L3_GND | BOTTOM | SOLDERMASK_BOTTOM | SILSKCREEN_BOTTOM | TYPE | SURFACE | MASK | CONDUCTOR | DIELECTRIC | PLANE | TOTAL THICKNESS | THICKNESS | 64 | TOLERANCE | +/- 10%
DIMENSION: (REF) | DIA MAX
User.11: C | A | 1 | 6.    SEE DETAIL A TO INSTALL CNMILLMAX2308 TO THE FOLLOWING LOCATION | 7.    SEE DETAIL B TO INSTALL CNMILLMAX2501 TO THE FOLLOWING LOCATION | 8.    INSTALL SHUNT 2 POS (M022926) TO THE FOLLOWING JUMPER. | TTP1,TP35,TP37,TP39,TP41,TP43,VBACKUP,VBATT,VOUT1,VOUT2,VOUT3,VOUT4 | NTC,PROG,TP6,TP42,TRKSS1,TRKSS2,VIN | LED_DRIVE, TIMER, EN, CHRG_LED, P13, P14, TRKSS1 AND TRKSS2 ON PIN 1 AND 2 | P2 AND ICHARGE ON PIN 2 AND 3 | SEE DETAIL C | DETAIL C | 2 | 3 | FOR D1 MANUALLY SHORT PIN 1,2, 3 AND EXPOSED PAD. | FILL WITH SOLDER LEAD AND SHORT THIS EXPOSED PAD
User.12: A | C | INSTALL STANDOFF (M025474) AT 4 PLACES
User.15: 3.5 MILS | ROHS COMPLIANCE NOTE:  HOMOGENOUS MATERIALS IN THIS BOARD SHALL BE COMPLIANT | THE EU RoHS DIRECTIVE 2002/95/EC
User.17: L2 GND | 08-      -08
User.18: L3 PWR | 08-      -09
User.25: 2
User.45: FIGURE | PCB | SECONDARY SIDE | PRIMARY SIDE | SIZE | 8.0 | 12.0 | 40.0 | 70.0 | 100.0 | 125.0 | PLATED | NON-PLATED | FINISHED HOLES IN MILS | ALL UNITS ARE IN MILS | QTY | 22 | 1354 | 30 | 12 | 4 | TOLERANCE/NOTES | .156 | .219
